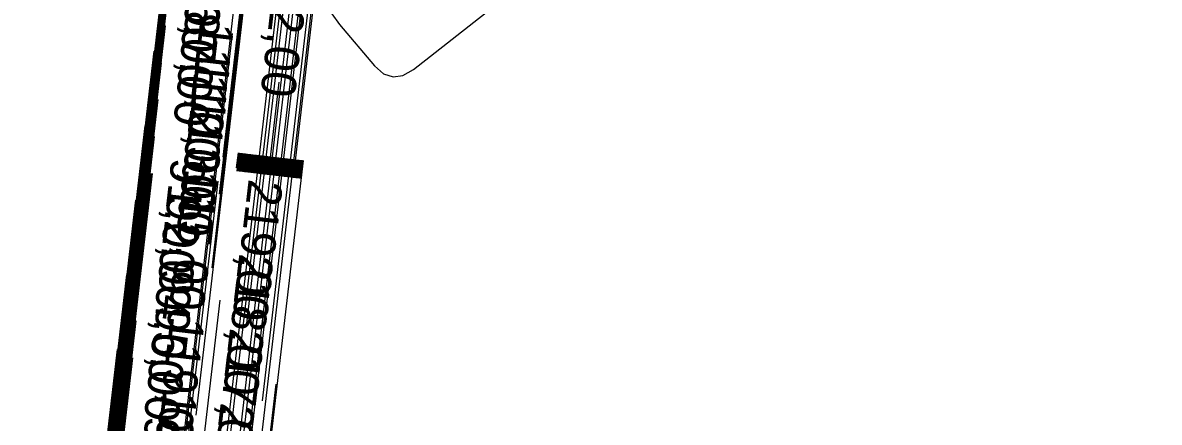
# Model space of a CAD drawing. Extents: x -500397 to -496810, y -1135552 to -1132176.
# Drawn here: x -500397 to -500331.1, y -1134708.3 to -1134685.2 of the extents above; entities that cross this region are included whole.
import ezdxf

# ---------------------------------------------------------------- set-up
doc = ezdxf.new("R2010")
doc.units = 0
doc.layers.add('30', color=7, linetype='Continuous')
doc.layers.add('40', color=7, linetype='Continuous')

msp = doc.modelspace()

# ---------------------------------------------------------------- linework, layer by layer
at = {"layer": '30'}
for points in [[(-500387.172, -1134737.454), (-500331.085, -1134256.995)], [(-500332.225, -1134267.69), (-500387.044, -1134737.277)], [(-500387.816, -1134738.339), (-500334.109, -1134278.277)], [(-500335.604, -1134301.879), (-500386.314, -1134736.273)], [(-500381.292, -1134694.179), (-500353.925, -1134459.748)], [(-500387.558, -1134737.985), (-500355.567, -1134463.937)], [(-500385.368, -1134692.998), (-500359.651, -1134472.701)], [(-500386.008, -1134699.408), (-500359.545, -1134472.714)], [(-500383.09, -1134707.111), (-500356.732, -1134481.325)], [(-500384.007, -1134702.624), (-500361.685, -1134511.412)], [(-500385.582, -1134695.134), (-500366.175, -1134528.891)], [(-500387.425, -1134728.512), (-500367.626, -1134558.908)], [(-500386.933, -1134707.946), (-500373.237, -1134590.621)], [(-500388.342, -1134738.221), (-500372.962, -1134606.474)], [(-500386.129, -1134660.947), (-500396.569, -1134750.38), (-500396.567, -1134750.485), (-500396.533, -1134750.568), (-500396.468, -1134750.631), (-500396.372, -1134750.671), (-500395.924, -1134750.792), (-500395.814, -1134750.827), (-500395.707, -1134750.87), (-500395.605, -1134750.921), (-500395.506, -1134750.981), (-500395.106, -1134751.248), (-500395.007, -1134751.313), (-500394.907, -1134751.376), (-500394.805, -1134751.438), (-500394.703, -1134751.498), (-500393.349, -1134752.284), (-500393.183, -1134752.384), (-500393.021, -1134752.487), (-500392.863, -1134752.596), (-500392.707, -1134752.709), (-500392.09, -1134753.172)], [(-500386.669, -1134665.264), (-500396.612, -1134750.439), (-500396.61, -1134750.539), (-500396.578, -1134750.619), (-500396.516, -1134750.678), (-500396.424, -1134750.717), (-500395.997, -1134750.832), (-500395.892, -1134750.864), (-500395.791, -1134750.905), (-500395.694, -1134750.954), (-500395.6, -1134751.012), (-500395.219, -1134751.265), (-500395.124, -1134751.327), (-500395.029, -1134751.388), (-500394.932, -1134751.447), (-500394.835, -1134751.504), (-500393.545, -1134752.253), (-500393.388, -1134752.347), (-500393.233, -1134752.446), (-500393.082, -1134752.55), (-500392.934, -1134752.657), (-500392.346, -1134753.098)], [(-500387.209, -1134669.582), (-500396.655, -1134750.499), (-500396.653, -1134750.593), (-500396.622, -1134750.669), (-500396.564, -1134750.725), (-500396.476, -1134750.762), (-500396.071, -1134750.871), (-500395.971, -1134750.902), (-500395.875, -1134750.941), (-500395.783, -1134750.988), (-500395.693, -1134751.042), (-500395.331, -1134751.283), (-500395.241, -1134751.342), (-500395.151, -1134751.399), (-500395.059, -1134751.455), (-500394.966, -1134751.51), (-500393.741, -1134752.221), (-500393.592, -1134752.311), (-500393.445, -1134752.405), (-500393.301, -1134752.503), (-500393.161, -1134752.606), (-500392.603, -1134753.024)], [(-500387.449, -1134672.562), (-500396.526, -1134750.321), (-500396.524, -1134750.431), (-500396.488, -1134750.518), (-500396.42, -1134750.583), (-500396.319, -1134750.626), (-500395.85, -1134750.753), (-500395.735, -1134750.789), (-500395.623, -1134750.834), (-500395.516, -1134750.888), (-500395.413, -1134750.951), (-500394.994, -1134751.23), (-500394.89, -1134751.298), (-500394.784, -1134751.364), (-500394.678, -1134751.429), (-500394.571, -1134751.493), (-500393.152, -1134752.316), (-500392.979, -1134752.42), (-500392.81, -1134752.529), (-500392.643, -1134752.643), (-500392.48, -1134752.761), (-500391.834, -1134753.246)], [(-500391.578, -1134753.32), (-500392.253, -1134752.813), (-500392.424, -1134752.689), (-500392.598, -1134752.57), (-500392.775, -1134752.456), (-500392.956, -1134752.348), (-500394.439, -1134751.487), (-500394.551, -1134751.421), (-500394.662, -1134751.353), (-500394.772, -1134751.283), (-500394.881, -1134751.212), (-500395.319, -1134750.92), (-500395.427, -1134750.855), (-500395.539, -1134750.798), (-500395.656, -1134750.751), (-500395.776, -1134750.713), (-500396.267, -1134750.581), (-500396.373, -1134750.536), (-500396.444, -1134750.468), (-500396.481, -1134750.377), (-500396.483, -1134750.262), (-500387.413, -1134672.566)], [(-500391.322, -1134753.394), (-500392.026, -1134752.865), (-500392.204, -1134752.735), (-500392.386, -1134752.611), (-500392.571, -1134752.493), (-500392.76, -1134752.379), (-500394.308, -1134751.481), (-500394.425, -1134751.412), (-500394.54, -1134751.341), (-500394.655, -1134751.269), (-500394.769, -1134751.194), (-500395.226, -1134750.89), (-500395.338, -1134750.821), (-500395.455, -1134750.762), (-500395.577, -1134750.713), (-500395.703, -1134750.674), (-500396.215, -1134750.536), (-500396.325, -1134750.489), (-500396.399, -1134750.418), (-500396.438, -1134750.323), (-500396.44, -1134750.203), (-500387.378, -1134672.57)], [(-500392.725, -1134753.047), (-500392.859, -1134752.95), (-500393.387, -1134752.554), (-500393.521, -1134752.457), (-500393.657, -1134752.364), (-500393.796, -1134752.275), (-500393.937, -1134752.19), (-500395.098, -1134751.516), (-500395.186, -1134751.464), (-500395.273, -1134751.411), (-500395.359, -1134751.356), (-500395.444, -1134751.301), (-500395.787, -1134751.072), (-500395.871, -1134751.021), (-500395.959, -1134750.977), (-500396.05, -1134750.94), (-500396.145, -1134750.91), (-500396.529, -1134750.807), (-500396.611, -1134750.772), (-500396.667, -1134750.719), (-500396.696, -1134750.647), (-500396.698, -1134750.558), (-500387.749, -1134673.9)], [(-500379.065, -1134684.694), (-500378.631, -1134685.312), (-500376.593, -1134687.694), (-500376.071, -1134688.155), (-500375.521, -1134688.345), (-500374.945, -1134688.266), (-500374.342, -1134687.917), (-500359.896, -1134676.583)], [(-500388.289, -1134678.218), (-500396.741, -1134750.617), (-500396.739, -1134750.701), (-500396.712, -1134750.769), (-500396.659, -1134750.819), (-500396.581, -1134750.852), (-500396.218, -1134750.95), (-500396.129, -1134750.978), (-500396.043, -1134751.013), (-500395.96, -1134751.054), (-500395.88, -1134751.103), (-500395.556, -1134751.318), (-500395.476, -1134751.371), (-500395.395, -1134751.423), (-500395.313, -1134751.473), (-500395.23, -1134751.522), (-500394.134, -1134752.158), (-500394, -1134752.238), (-500393.869, -1134752.322), (-500393.74, -1134752.41), (-500393.614, -1134752.502), (-500393.115, -1134752.876), (-500392.989, -1134752.968), (-500392.86, -1134753.056)], [(-500388.089, -1134678.972), (-500396.397, -1134750.144), (-500396.395, -1134750.269), (-500396.355, -1134750.368), (-500396.277, -1134750.442), (-500396.163, -1134750.491), (-500395.629, -1134750.634), (-500395.498, -1134750.675), (-500395.372, -1134750.727), (-500395.25, -1134750.788), (-500395.132, -1134750.859), (-500394.656, -1134751.177), (-500394.538, -1134751.254), (-500394.418, -1134751.33), (-500394.298, -1134751.403), (-500394.176, -1134751.475), (-500392.564, -1134752.411), (-500392.367, -1134752.529), (-500392.174, -1134752.653), (-500391.985, -1134752.782), (-500391.8, -1134752.917), (-500391.066, -1134753.468)], [(-500390.809, -1134753.542), (-500391.573, -1134752.969), (-500391.766, -1134752.828), (-500391.962, -1134752.694), (-500392.163, -1134752.565), (-500392.367, -1134752.443), (-500394.044, -1134751.469), (-500394.171, -1134751.395), (-500394.296, -1134751.318), (-500394.42, -1134751.239), (-500394.543, -1134751.159), (-500395.039, -1134750.829), (-500395.161, -1134750.755), (-500395.288, -1134750.691), (-500395.419, -1134750.638), (-500395.555, -1134750.595), (-500396.11, -1134750.445), (-500396.23, -1134750.395), (-500396.31, -1134750.318), (-500396.352, -1134750.215), (-500396.354, -1134750.085), (-500388.053, -1134678.976)], [(-500391.346, -1134753.021), (-500391.546, -1134752.875), (-500391.75, -1134752.735), (-500391.959, -1134752.602), (-500392.171, -1134752.474), (-500393.912, -1134751.464), (-500394.044, -1134751.386), (-500394.174, -1134751.306), (-500394.303, -1134751.225), (-500394.431, -1134751.141), (-500394.945, -1134750.799), (-500395.072, -1134750.721), (-500395.204, -1134750.655), (-500395.34, -1134750.6), (-500395.482, -1134750.556), (-500396.058, -1134750.4), (-500396.182, -1134750.348), (-500396.265, -1134750.268), (-500396.309, -1134750.161), (-500396.312, -1134750.026), (-500388.018, -1134678.98)], [(-500391.678, -1134743.652), (-500384.18, -1134679.428)], [(-500396.783, -1134750.676), (-500388.829, -1134682.536)], [(-500388.729, -1134685.381), (-500396.269, -1134749.967), (-500396.266, -1134750.107), (-500396.221, -1134750.218), (-500396.134, -1134750.301), (-500396.006, -1134750.355), (-500395.408, -1134750.516), (-500395.261, -1134750.562), (-500395.12, -1134750.619), (-500394.983, -1134750.688), (-500394.852, -1134750.768), (-500394.318, -1134751.123), (-500394.186, -1134751.21), (-500394.052, -1134751.295), (-500393.917, -1134751.377), (-500393.781, -1134751.458), (-500391.975, -1134752.506), (-500391.755, -1134752.638), (-500391.539, -1134752.777), (-500391.327, -1134752.921), (-500391.119, -1134753.072)], [(-500384.856, -1134685.834), (-500391.592, -1134743.533)], [(-500396.826, -1134750.735), (-500389.369, -1134686.853)], [(-500390.892, -1134753.124), (-500391.107, -1134752.968), (-500391.327, -1134752.818), (-500391.55, -1134752.674), (-500391.779, -1134752.538), (-500393.649, -1134751.452), (-500393.79, -1134751.369), (-500393.93, -1134751.283), (-500394.069, -1134751.195), (-500394.206, -1134751.106), (-500394.758, -1134750.738), (-500394.894, -1134750.655), (-500395.036, -1134750.584), (-500395.182, -1134750.524), (-500395.335, -1134750.477), (-500395.953, -1134750.31), (-500396.086, -1134750.254), (-500396.176, -1134750.168), (-500396.223, -1134750.053), (-500396.226, -1134749.908), (-500388.942, -1134687.518)], [(-500382.749, -1134694.009), (-500382.122, -1134688.64)], [(-500389.156, -1134689.655), (-500396.183, -1134749.849), (-500396.18, -1134749.999), (-500396.132, -1134750.118), (-500396.039, -1134750.206), (-500395.901, -1134750.265), (-500395.261, -1134750.437), (-500395.104, -1134750.487), (-500394.952, -1134750.548), (-500394.806, -1134750.622), (-500394.665, -1134750.707), (-500394.093, -1134751.088), (-500393.951, -1134751.181), (-500393.808, -1134751.272), (-500393.663, -1134751.36), (-500393.517, -1134751.446), (-500391.582, -1134752.569), (-500391.346, -1134752.711), (-500391.115, -1134752.859), (-500390.888, -1134753.014), (-500390.666, -1134753.176)], [(-500389.909, -1134691.171), (-500396.869, -1134750.794)], [(-500389.369, -1134691.791), (-500396.14, -1134749.79), (-500396.137, -1134749.945), (-500396.087, -1134750.068), (-500395.991, -1134750.159), (-500395.849, -1134750.22), (-500395.187, -1134750.398), (-500395.025, -1134750.449), (-500394.868, -1134750.512), (-500394.717, -1134750.588), (-500394.571, -1134750.677), (-500393.981, -1134751.07), (-500393.834, -1134751.166), (-500393.686, -1134751.26), (-500393.536, -1134751.351), (-500393.385, -1134751.441), (-500391.386, -1134752.601), (-500391.142, -1134752.747), (-500390.903, -1134752.901), (-500390.669, -1134753.061)], [(-500384.51, -1134692.742), (-500384.612, -1134693.616)], [(-500384.474, -1134692.746), (-500384.576, -1134693.62)], [(-500384.561, -1134693.797), (-500384.439, -1134692.751)], [(-500384.403, -1134692.755), (-500384.526, -1134693.801)], [(-500384.368, -1134692.759), (-500384.49, -1134693.806)], [(-500384.332, -1134692.763), (-500384.454, -1134693.81)], [(-500384.297, -1134692.767), (-500384.419, -1134693.814)], [(-500384.261, -1134692.771), (-500384.383, -1134693.818)], [(-500384.348, -1134693.822), (-500384.226, -1134692.775)], [(-500384.312, -1134693.826), (-500384.19, -1134692.78)], [(-500384.277, -1134693.83), (-500384.155, -1134692.784)], [(-500384.119, -1134692.788), (-500384.241, -1134693.835)], [(-500384.084, -1134692.792), (-500384.206, -1134693.839)], [(-500384.17, -1134693.843), (-500384.048, -1134692.796)], [(-500384.012, -1134692.8), (-500384.135, -1134693.847)], [(-500384.099, -1134693.851), (-500383.977, -1134692.804)], [(-500383.941, -1134692.809), (-500384.064, -1134693.855)], [(-500384.028, -1134693.859), (-500383.906, -1134692.813)], [(-500383.87, -1134692.817), (-500383.993, -1134693.864)], [(-500383.835, -1134692.821), (-500383.957, -1134693.868)], [(-500383.799, -1134692.825), (-500383.921, -1134693.872)], [(-500383.764, -1134692.829), (-500383.886, -1134693.876)], [(-500383.85, -1134693.88), (-500383.728, -1134692.833)], [(-500383.693, -1134692.838), (-500383.815, -1134693.884)], [(-500383.779, -1134693.888), (-500383.657, -1134692.842)], [(-500383.622, -1134692.846), (-500383.744, -1134693.893)], [(-500383.708, -1134693.897), (-500383.586, -1134692.85)], [(-500380.743, -1134693.182), (-500385.671, -1134735.388), (-500385.641, -1134736.758), (-500385.201, -1134737.849), (-500384.35, -1134738.663), (-500383.089, -1134739.197), (-500377.22, -1134740.779), (-500375.778, -1134741.23), (-500374.387, -1134741.793), (-500373.046, -1134742.468), (-500371.756, -1134743.254), (-500366.516, -1134746.742), (-500365.215, -1134747.594), (-500363.901, -1134748.426), (-500362.574, -1134749.237), (-500361.235, -1134750.028), (-500343.499, -1134760.322)], [(-500383.551, -1134692.854), (-500383.673, -1134693.901)], [(-500383.637, -1134693.905), (-500383.515, -1134692.858)], [(-500383.479, -1134692.863), (-500383.602, -1134693.909)], [(-500383.566, -1134693.913), (-500383.444, -1134692.867)], [(-500383.531, -1134693.918), (-500383.408, -1134692.871)], [(-500383.495, -1134693.922), (-500383.373, -1134692.875)], [(-500383.337, -1134692.879), (-500383.46, -1134693.926)], [(-500383.302, -1134692.883), (-500383.424, -1134693.93)], [(-500383.231, -1134692.892), (-500383.353, -1134693.938)], [(-500383.317, -1134693.942), (-500383.195, -1134692.896)], [(-500383.16, -1134692.9), (-500383.282, -1134693.947)], [(-500383.124, -1134692.904), (-500383.246, -1134693.951)], [(-500383.089, -1134692.908), (-500383.211, -1134693.955)], [(-500383.018, -1134692.916), (-500383.14, -1134693.963)], [(-500383.104, -1134693.967), (-500382.982, -1134692.921)], [(-500383.069, -1134693.971), (-500382.947, -1134692.925)], [(-500383.033, -1134693.976), (-500382.911, -1134692.929)], [(-500382.84, -1134692.937), (-500382.962, -1134693.984)], [(-500382.927, -1134693.988), (-500382.804, -1134692.941)], [(-500382.769, -1134692.945), (-500382.891, -1134693.992)], [(-500382.856, -1134693.996), (-500382.733, -1134692.95)], [(-500382.698, -1134692.954), (-500382.82, -1134694)], [(-500382.784, -1134694.005), (-500382.662, -1134692.958)], [(-500382.591, -1134692.966), (-500382.713, -1134694.013)], [(-500382.556, -1134692.97), (-500382.678, -1134694.017)], [(-500382.485, -1134692.979), (-500382.607, -1134694.025)], [(-500382.571, -1134694.03), (-500382.449, -1134692.983)], [(-500382.536, -1134694.034), (-500382.414, -1134692.987)], [(-500382.378, -1134692.991), (-500382.5, -1134694.038)], [(-500382.465, -1134694.042), (-500382.342, -1134692.995)], [(-500382.394, -1134694.05), (-500382.271, -1134693.004)], [(-500382.358, -1134694.054), (-500382.236, -1134693.008)], [(-500382.323, -1134694.059), (-500382.2, -1134693.012)], [(-500382.287, -1134694.063), (-500382.165, -1134693.016)], [(-500382.251, -1134694.067), (-500382.129, -1134693.02)], [(-500382.094, -1134693.024), (-500382.216, -1134694.071)], [(-500382.058, -1134693.028), (-500382.18, -1134694.075)], [(-500382.023, -1134693.033), (-500382.145, -1134694.079)], [(-500382.074, -1134694.088), (-500381.952, -1134693.041)], [(-500381.916, -1134693.045), (-500382.038, -1134694.092)], [(-500381.845, -1134693.053), (-500381.967, -1134694.1)], [(-500381.932, -1134694.104), (-500381.809, -1134693.057)], [(-500381.774, -1134693.062), (-500381.896, -1134694.108)], [(-500381.861, -1134694.112), (-500381.738, -1134693.066)], [(-500381.825, -1134694.117), (-500381.703, -1134693.07)], [(-500381.79, -1134694.121), (-500381.667, -1134693.074)], [(-500381.754, -1134694.125), (-500381.632, -1134693.078)], [(-500381.596, -1134693.082), (-500381.718, -1134694.129)], [(-500381.561, -1134693.087), (-500381.683, -1134694.133)], [(-500381.525, -1134693.091), (-500381.647, -1134694.137)], [(-500381.612, -1134694.142), (-500381.49, -1134693.095)], [(-500381.541, -1134694.15), (-500381.419, -1134693.103)], [(-500381.383, -1134693.107), (-500381.505, -1134694.154)], [(-500381.47, -1134694.158), (-500381.348, -1134693.111)], [(-500381.312, -1134693.116), (-500381.434, -1134694.162)], [(-500381.241, -1134693.124), (-500381.363, -1134694.171)], [(-500381.328, -1134694.175), (-500381.205, -1134693.128)], [(-500381.257, -1134694.183), (-500381.134, -1134693.136)], [(-500381.099, -1134693.14), (-500381.221, -1134694.187)], [(-500381.063, -1134693.145), (-500381.185, -1134694.191)], [(-500381.15, -1134694.195), (-500381.028, -1134693.149)], [(-500381.114, -1134694.2), (-500380.992, -1134693.153)], [(-500381.079, -1134694.204), (-500380.957, -1134693.157)], [(-500380.921, -1134693.161), (-500381.043, -1134694.208)], [(-500381.008, -1134694.212), (-500380.886, -1134693.165)], [(-500380.85, -1134693.169), (-500380.972, -1134694.216)], [(-500380.815, -1134693.174), (-500380.937, -1134694.22)], [(-500380.779, -1134693.178), (-500380.901, -1134694.224)], [(-500389.583, -1134693.928), (-500396.097, -1134749.731), (-500396.094, -1134749.891), (-500396.042, -1134750.018), (-500395.943, -1134750.112), (-500395.797, -1134750.174), (-500395.114, -1134750.358), (-500394.946, -1134750.411), (-500394.784, -1134750.476), (-500394.628, -1134750.555), (-500394.478, -1134750.646), (-500393.868, -1134751.052), (-500393.717, -1134751.152), (-500393.564, -1134751.248), (-500393.409, -1134751.343), (-500393.254, -1134751.435), (-500391.19, -1134752.633), (-500390.938, -1134752.784), (-500390.691, -1134752.942), (-500390.449, -1134753.107)], [(-500389.547, -1134693.932), (-500396.054, -1134749.672), (-500396.051, -1134749.837), (-500395.998, -1134749.968), (-500395.896, -1134750.065), (-500395.744, -1134750.129), (-500395.04, -1134750.319), (-500394.867, -1134750.373), (-500394.7, -1134750.441), (-500394.539, -1134750.522), (-500394.384, -1134750.616), (-500393.755, -1134751.035), (-500393.599, -1134751.137), (-500393.442, -1134751.237), (-500393.282, -1134751.334), (-500393.122, -1134751.429), (-500390.994, -1134752.664), (-500390.734, -1134752.82), (-500390.479, -1134752.983), (-500390.23, -1134753.154)], [(-500390.268, -1134753.024), (-500390.53, -1134752.856), (-500390.797, -1134752.696), (-500392.99, -1134751.423), (-500393.156, -1134751.325), (-500393.32, -1134751.225), (-500393.482, -1134751.122), (-500393.643, -1134751.017), (-500394.291, -1134750.586), (-500394.45, -1134750.488), (-500394.616, -1134750.405), (-500394.788, -1134750.335), (-500394.966, -1134750.28), (-500395.692, -1134750.084), (-500395.848, -1134750.018), (-500395.953, -1134749.917), (-500396.008, -1134749.783), (-500396.011, -1134749.613), (-500389.512, -1134693.936)], [(-500390.056, -1134753.066), (-500390.326, -1134752.893), (-500390.601, -1134752.727), (-500392.858, -1134751.417), (-500393.029, -1134751.317), (-500393.198, -1134751.213), (-500393.365, -1134751.108), (-500393.53, -1134750.999), (-500394.197, -1134750.555), (-500394.361, -1134750.455), (-500394.532, -1134750.369), (-500394.709, -1134750.298), (-500394.893, -1134750.24), (-500395.64, -1134750.039), (-500395.8, -1134749.971), (-500395.909, -1134749.867), (-500395.965, -1134749.728), (-500395.968, -1134749.554), (-500389.476, -1134693.94)], [(-500385.674, -1134694.384), (-500391.377, -1134743.238)], [(-500390.449, -1134695.489), (-500396.912, -1134750.853)], [(-500390.989, -1134699.807), (-500396.955, -1134750.912)], [(-500390.262, -1134741.704), (-500385.541, -1134701.266)], [(-500390.436, -1134702.474), (-500395.925, -1134749.495), (-500395.922, -1134749.674), (-500395.864, -1134749.817), (-500395.753, -1134749.924), (-500395.587, -1134749.994), (-500394.819, -1134750.201), (-500394.63, -1134750.26), (-500394.448, -1134750.334), (-500394.273, -1134750.422), (-500394.104, -1134750.525), (-500393.418, -1134750.981), (-500393.247, -1134751.093), (-500393.075, -1134751.202), (-500392.902, -1134751.308), (-500392.727, -1134751.412), (-500390.405, -1134752.759), (-500390.122, -1134752.929), (-500389.844, -1134753.107)], [(-500391.529, -1134704.124), (-500396.998, -1134750.971)], [(-500389.632, -1134753.148), (-500389.918, -1134752.965), (-500390.208, -1134752.791), (-500392.595, -1134751.406), (-500392.775, -1134751.299), (-500392.953, -1134751.19), (-500393.13, -1134751.078), (-500393.305, -1134750.964), (-500394.01, -1134750.494), (-500394.184, -1134750.389), (-500394.364, -1134750.298), (-500394.551, -1134750.222), (-500394.745, -1134750.161), (-500395.535, -1134749.949), (-500395.705, -1134749.877), (-500395.819, -1134749.767), (-500395.879, -1134749.62), (-500395.882, -1134749.436), (-500390.65, -1134704.611)], [(-500389.42, -1134753.19), (-500389.713, -1134753.002), (-500390.012, -1134752.822), (-500392.463, -1134751.4), (-500392.648, -1134751.291), (-500392.831, -1134751.179), (-500393.013, -1134751.064), (-500393.193, -1134750.946), (-500393.917, -1134750.464), (-500394.095, -1134750.355), (-500394.28, -1134750.262), (-500394.473, -1134750.184), (-500394.672, -1134750.122), (-500395.483, -1134749.903), (-500395.657, -1134749.83), (-500395.775, -1134749.717), (-500395.835, -1134749.566), (-500395.84, -1134749.377), (-500390.614, -1134704.615)], [(-500343.695, -1134760.29), (-500361.367, -1134750.034), (-500362.701, -1134749.246), (-500364.023, -1134748.437), (-500365.332, -1134747.609), (-500366.628, -1134746.76), (-500371.849, -1134743.284), (-500373.135, -1134742.501), (-500374.471, -1134741.829), (-500375.857, -1134741.268), (-500377.294, -1134740.818), (-500383.141, -1134739.242), (-500384.398, -1134738.71), (-500385.246, -1134737.9), (-500385.684, -1134736.812), (-500385.713, -1134735.447), (-500382.293, -1134706.144)]]:
    msp.add_lwpolyline(points, dxfattribs=at)

# ---------------------------------------------------------------- texts
at = {"layer": '40'}
for s, p in [('85,00', (-500387.074, -1134680.169)), ('222,00', (-500382.268, -1134681.262)), ('86,00', (-500387.288, -1134682.306)), ('87,00', (-500387.501, -1134684.442)), ('111,00', (-500386.709, -1134685.065)), ('112,00', (-500386.923, -1134687.201)), ('113,00', (-500387.136, -1134689.338)), ('91,00', (-500388.355, -1134692.989)), ('115,00', (-500387.563, -1134693.611)), ('219,00', (-500383.888, -1134694.215)), ('92,00', (-500388.568, -1134695.125)), ('218,00', (-500384.428, -1134698.533)), ('94,00', (-500388.995, -1134699.398)), ('95,00', (-500389.208, -1134701.535)), ('119,00', (-500388.417, -1134702.157)), ('217,00', (-500384.968, -1134702.851)), ('121,00', (-500388.843, -1134706.43)), ('216,00', (-500385.508, -1134707.169)), ('98,00', (-500389.849, -1134707.945))]:
    msp.add_text(s, height=2, rotation=263.34157, dxfattribs=at).set_placement(p)

doc.saveas('drawing.dxf')
